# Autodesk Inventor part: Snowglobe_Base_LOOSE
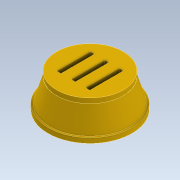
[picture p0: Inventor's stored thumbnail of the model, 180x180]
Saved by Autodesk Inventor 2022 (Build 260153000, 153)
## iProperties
Created: 2021-12
Part Number: Snowglobe_Base_LOOSE
Material: Generic
Document SubType Name: Modeling
Designer: allis
Density: 1 g/cm^3
Appearance: Gold
Author: allis
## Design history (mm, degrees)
sketch "Sketch1"
  geometry: C1 r 31.75 at (0, 0); 1 further point
  constraints: 1 centre point, 1 coincident
  dimensions: "d0" = 63.5 diameter of C1
workplane "Work Plane1"
sketch "Sketch2"
  geometry: C1 r 24.13 at (0, 0); 1 further point
  constraints: 1 centre point, 1 coincident
  dimensions: "d2" = 48.26 diameter of C1
loft "Loft1" sketch "Sketch2" dims "d3" = 0, "d4" = 90 deg, "d5" = 0, "d6" = 90 deg
sketch "Sketch3"
  geometry: L1 (-12.7, -12.89)-(12.7, -12.89); L2 (12.7, -12.89)-(12.7, 12.89); L3 (12.7, 12.89)-(-12.7, 12.89); L4 (-12.7, 12.89)-(-12.7, -12.89); L5 (-12.7, -12.89)-(-9.377, -12.89); L6 (-9.377, -12.89)-(-9.377, 12.89); L7 (-9.377, 12.89)-(-12.7, 12.89); L8 (-12.7, 12.89)-(-12.7, -12.89); L9 (12.7, -12.89)-(9.377, -12.89); L10 (9.377, -12.89)-(9.377, 12.89); L11 (9.377, 12.89)-(12.7, 12.89); L12 (12.7, 12.89)-(12.7, -12.89); L13 (-1.637, 12.89)-(1.637, 12.89); L14 (1.637, 12.89)-(1.637, -12.89); L15 (1.637, -12.89)-(-1.637, -12.89); L16 (-1.637, -12.89)-(-1.637, 12.89); 5 further points
  constraints: 32 end point, 8 parallel, 4 horizontal, 4 perpendicular, 4 point on line
  dimensions: "d7" = 12.7 distance from line of point (0, 0) L4; "d8" = 12.7 distance from line of L2 point (0, 0); "d9" = 12.8905 distance from line of point (0, 0) L1; "d10" = 12.8905 distance from line of point (0, 0) L3; "d11" = 3.32257 distance between parallel lines of L6 L8; "d12" = 3.32257 distance between parallel lines of L2 L10; "d13" = 1.63709 distance from line of point (0, 0) L14; "d14" = 1.63709 distance from line of point (0, 0) L16
extrude "Extrusion1" cut sketch "Sketch3" distance "d15" = 19.05; taper "d16" = 0 deg
sketch "Sketch4"
  geometry: L1 (0, -31.75)-(0, 31.75) reference; L2 (25.4, 24.13)-(25.4, -24.13) reference; L3 (0, 0)-(3.81, 0); L4 (3.81, 0)-(3.81, -32.004); L5 (3.81, -32.004)-(0, -32.004); L6 (0, -32.004)-(0, 0); L7 (44.897, 0)-(-16.323, 0); L8 (25.4, 12.89)-(25.4, -12.89) reference; L9 (25.4, 0)-(21.59, 0); L10 (21.59, 0)-(21.59, -25.4); L11 (21.59, -25.4)-(25.4, -25.4); L12 (25.4, -25.4)-(25.4, 0); L13 (0, -31.75)-(25.4, -24.13) reference; 9 further points
  constraints: 18 end point, 4 parallel, 3 horizontal, 3 perpendicular, 1 midpoint
  dimensions: "d18" = 32.004 distance between parallel lines of L3 L5; "d19" = 3.81 distance between parallel lines of L1 L4; "d20" = 3.81 distance between parallel lines of L12 L10; "d22" = 25.4 distance between parallel lines of L11 L7
revolve "Revolution1" sketch "Sketch4" stored, may be unused: angle "d17" = 360 deg
feature "Move Body1"
body "Solid1"
node "Projected Loop1"
other parameters: "d1" = 25.4, "d23" = 90 deg
